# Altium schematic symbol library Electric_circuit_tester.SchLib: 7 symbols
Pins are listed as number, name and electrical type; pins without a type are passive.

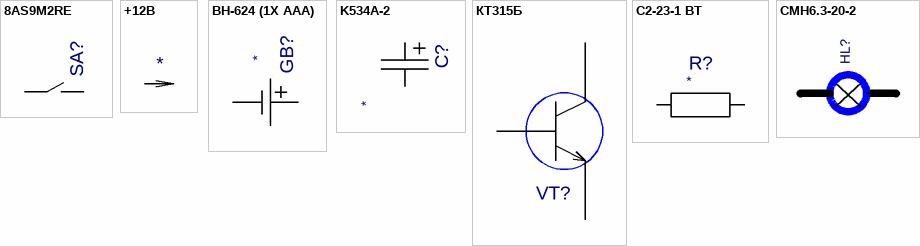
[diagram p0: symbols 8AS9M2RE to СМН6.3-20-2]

## 8AS9M2RE
designator SA?  (value not drawn)
footprint 8AS9M2RE
pins: 1, 2

## +12B
designator PWR?  (value not drawn)
pins: 1 +12B (power)

## BH-624 (1X AAA)
designator GB?  (value not drawn)
footprint BH-624 (1X AAA)
pins: 1, 2

## K534A-2
designator C?  (value not drawn)
footprint K534A-2
pins: 1 I/OA, 2 I/OB

## КТ315Б
designator VT?  (value not drawn)
footprint KT13
pins: 1 E, 2 B, 3 K

## С2-23-1 ВТ
designator R?  (value not drawn)
footprint C2-33H-1W_17.5MM
pins: 1 I/O0, 2 I/O1

## СМН6.3-20-2
designator HL?  (value not drawn)
footprint HL_MINI
pins: 1, 2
